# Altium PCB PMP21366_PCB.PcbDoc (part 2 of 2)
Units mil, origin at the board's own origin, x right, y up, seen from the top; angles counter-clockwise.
Board outline 5900 x 4700 mil, 2 copper layers (Top Layer, Bottom Layer), stack 62 mil thick; 89 components, 44 nets, 220 pads, 54 vias.
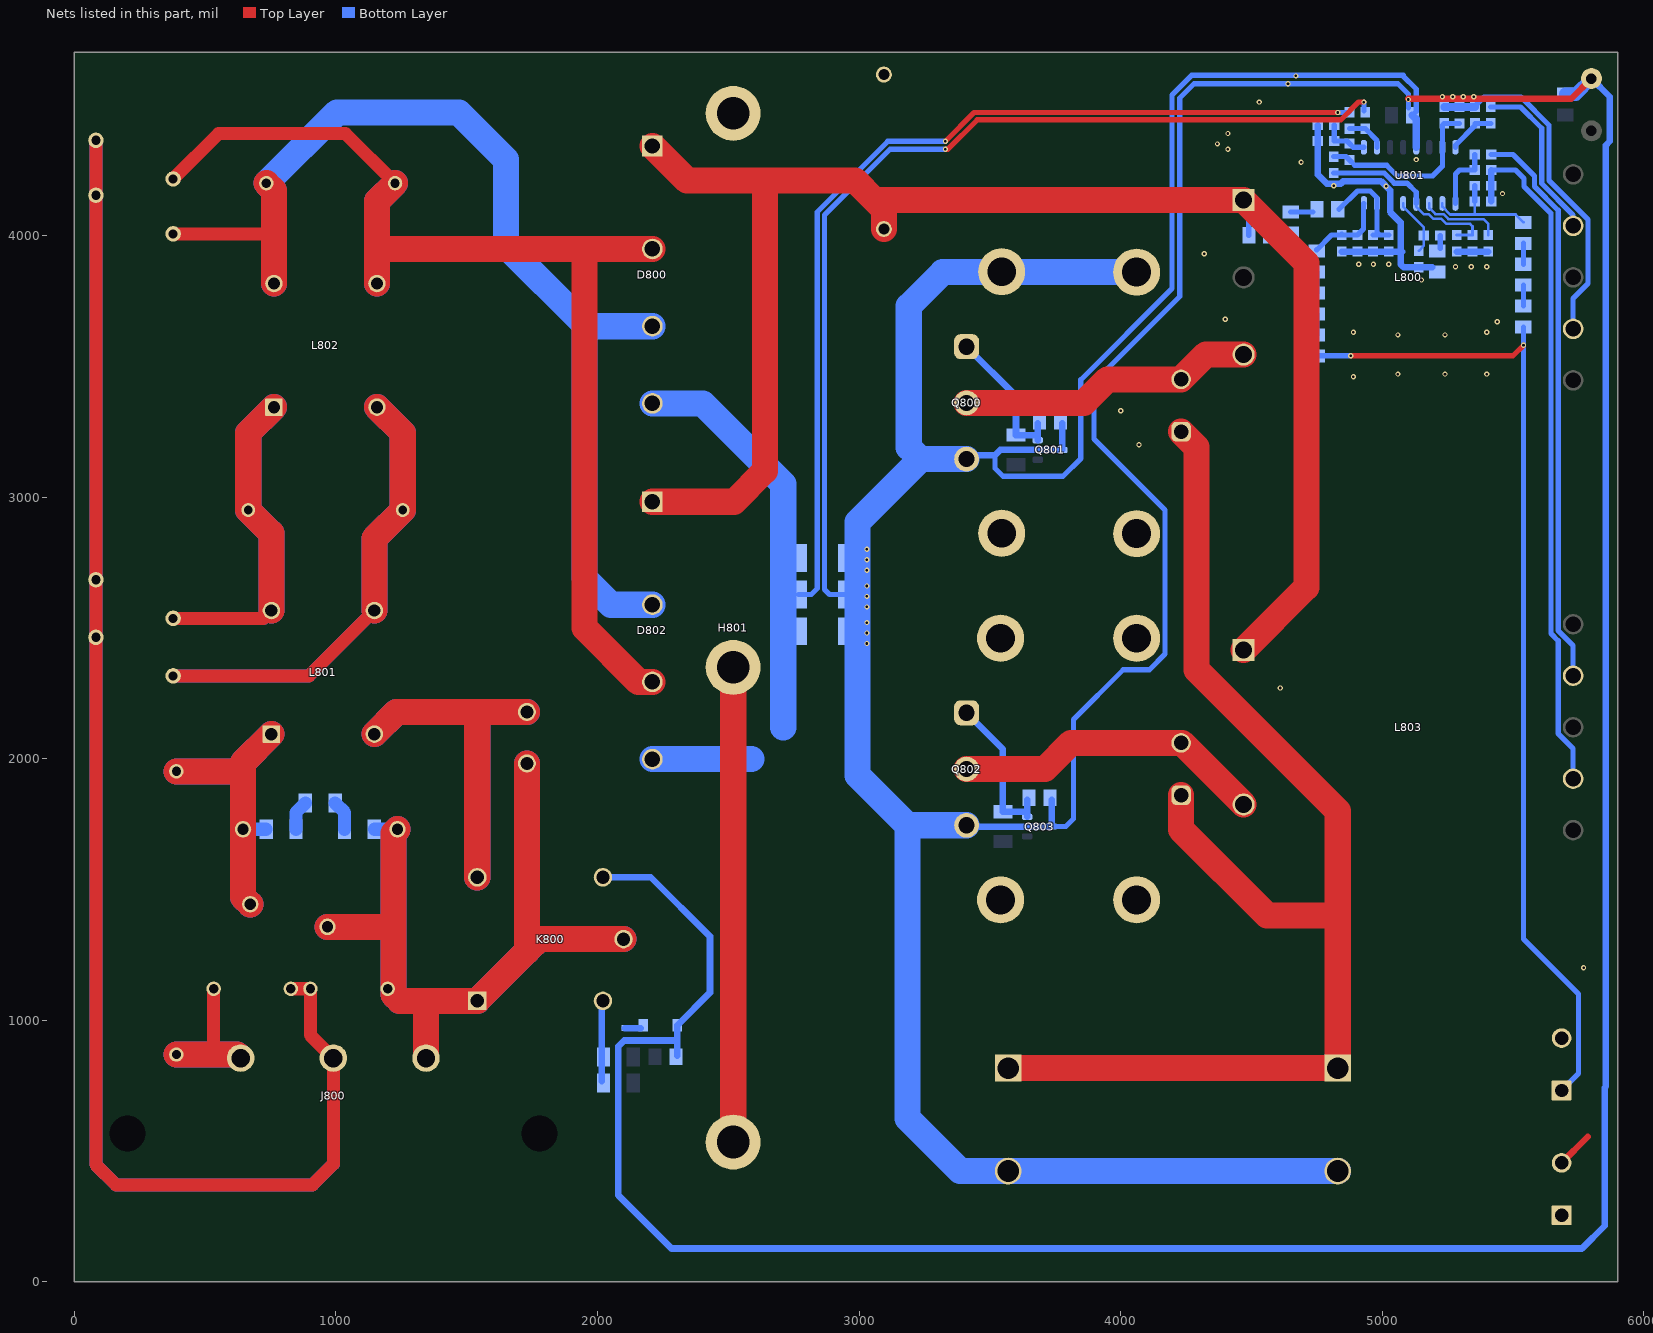
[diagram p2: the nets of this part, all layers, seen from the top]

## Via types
v1: diameter 20, hole 10, Top Layer to Bottom Layer, 54 vias

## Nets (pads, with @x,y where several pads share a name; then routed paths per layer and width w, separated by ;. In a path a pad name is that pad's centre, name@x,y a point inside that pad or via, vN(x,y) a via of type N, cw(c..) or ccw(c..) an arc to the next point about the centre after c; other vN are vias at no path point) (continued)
GND1: C810.2 C811.2 C812.2 C814.1 C815.2 C816.2 C817.2 C818.2 C819.2 C820.2 C821.2 C822.2 C823.2 C824.2 C825.2 C826.2 C827.2 D804.1 GND.1 H800.1 H800.2 H802.1 H802.2 H803.1 H803.2 H804.1 H804.2 J802.1 J802.2 K800.5 L800.5 L803.5 Q800.3 Q801.3 Q802.3 Q803.3 R803.2 R804.2 R805.2 R806.1 R814.1 R824.1 R829.1 R831.1 R832.1 R833.1 R834.1 U801.6 U801.13 | length 34843.4
  Top Layer w20: v1(3330,4330) 3339.42,4330 3451.55,4442.13 4841.55,4442.13 4909.42,4510 v1(4930,4510)
  Top Layer w25: v1@5100,4522.5 5722.5,4522.5 GND.1@5800,4600 ; J802.2@5685.67,454.26 5785.67,554.26
  Bottom Layer w20: R805.2@2950.55,2627.09 2887.56,2627.09 2867.87,2646.77 2867.87,4078.45 3119.42,4330 v1(3330,4330) ; 3520,3160 3520,3110 3550.55,3079.45 3779.45,3079.45 3847.87,3147.87 3847.87,3448.45 4196.75,3797.33 4196.75,4537.33 4271.55,4612.13 5080,4612.13 5080,4610 5130,4560 5130,4475 C817.2@5115,4460 ; Q803.3@3737.24,1740 3790,1740 3820,1770 3820,2150 4010,2340 4110,2340 4170,2400 4170,2950 3897.87,3222.13 3897.87,3439.03 4225.75,3766.91 4225.75,4525.75 4280,4580 5060,4580 5100,4540 v1(5100,4520) C817.2@5100,4488.54 ; C820.2@4930,4476.5 v1(4930,4510) ; C815.2@5355,4491.5 5355,4495.16 5388.9,4529.06 5530.36,4529.06 5637.87,4421.55 5637.87,4209.85 5787.17,4060.56 5787.17,3816.29 5729.92,3759.04 L800.5@5729.92,3643.15 ; C816.2@5416.5,4250 5510,4250 5542.13,4217.87 5542.13,4187.34 5644.8,4084.66 5644.8,2478.44 5672.68,2450.57 5672.68,2096.29 5729.92,2039.04 L803.5@5729.92,1923.15
  Bottom Layer w25: K800.5@2020.79,1546.22 2203.78,1546.22 2430,1320 2430,1105.53 D804.1@2304.47,980 2304.47,922.23 ; C814.1@2304.47,864.47 2304.47,922.23 ; Q802.3@3416,1740 Q803.3@3737.24,1740 R814.1@3737.24,1842.76 ; Q800.3@3426,3160 3520,3160 3540,3180 Q801.3@3777.24,3180 R806.1@3777.24,3282.76 ; C819.2@4753.5,4421.3 R829.1@4753.5,4361.3 4753.5,4232.8 4787.86,4198.44 4842.14,4198.44 4851.82,4208.13 4995,4208.13 5030,4173.13 U801.6@5030,4122.72 5030,4090 5070,4050 5070,3890 5081.5,3878.5 C823.2@5140,3878.5 C827.2@5191.5,3878.5 ; R831.1@4845,3938.5 C821.2@4905,3938.5 5076.5,3938.5 ; C826.2@5285,3938.5 R834.1@5345,3938.5 R833.1@5405,3938.5 ; C818.2@5416.5,4130 C816.2@5416.5,4250 ; GND.1@5800,4600 5870,4530 5870,4360 5855.37,4345.37 5855.37,747.03 5850.41,742.07 5850.41,213.92 5763.62,127.13 2282.87,127.13 2080,330 2080,900 2102.23,922.23 2304.47,922.23
  Bottom Layer w29.53: C817.2@5115,4460 5130,4445 U801.13@5130,4337.28 ; C825.2@5236.93,4491.5 C815.2@5355,4491.5
  Bottom Layer w50: C812.2@5700,4540 5740,4540 GND.1@5800,4600
  Bottom Layer w100: Q802.3@3411,1745 3185,1745 ; Q800.3@3411,3145 3235,3145 ; H800.2@4061,3860 3320,3860 3190,3730 3190,3190 3235,3145 ; C811.2@4830,423.15 C810.2@3570,423.15 3386.85,423.15 3185,625 3185,1745 ; 3185,1745 2994.6,1935.4 2994.6,2904.6 3235,3145
  other v1: 5770,1200 4610,2270 3030,2440 3030,2480 3030,2520 3030,2580 3030,2620 3030,2660 3030,2720 3030,2760 3030,2800 4070,3200 4000,3330 4890,3460 5060,3470 5240,3470 5400,3470 5060,3620 5240,3620 4890,3630 5400,3630 5440,3670 4400,3680 5150,3830 5280,3880 5340,3880 5400,3880 4910,3890 4966.31,3890.43 5025,3890 4320,3930 5460,4160 5015,4188.13 4815,4190 4690,4280 5130,4290 4410,4330 4370,4350 4410,4390 4530,4510 5230,4530 5270,4530 5310,4530 5350,4530 4640,4580 4670,4610
NetC801_2: C801.2 F800.2 J800.1 | length 1005.3
  Top Layer w50: 532.36,868.66 C801.2@532.36,1120
  Top Layer w100: F800.2@390,868.66 532.36,868.66 622.01,868.66 J800.1@635.67,855
  Bottom Layer w50: 532.36,868.66 C801.2@532.36,1120
  Bottom Layer w100: F800.2@390,868.66 532.36,868.66 622.01,868.66 J800.1@635.67,855
NetC802_2: C802.2 C805.1 L801.4 L802.1 | length 2485.8
  Top Layer w50: C802.2@377.64,2536.18 723.11,2536.18 L801.4@753.15,2566.22
  Top Layer w100: L801.4@753.15,2566.22 753.15,2861.57 C805.1@664.72,2950 664.72,3245.35 L802.1@763.15,3343.78
  Bottom Layer w50: C802.2@377.64,2536.18 723.11,2536.18 L801.4@753.15,2566.22
  Bottom Layer w100: L801.4@753.15,2566.22 753.15,2861.57 C805.1@664.72,2950 664.72,3245.35 L802.1@763.15,3343.78
NetC803_2: C803.2 C806.1 D800.3 D802.2 L802.4 | length 4545.1
  Top Layer w50: C803.2@377.64,4006.18 739.33,4006.18
  Top Layer w100: C806.1@733.94,4200 763.15,4170.79 L802.4@763.15,3816.22
  Bottom Layer w100: L802.4@763.15,3816.22 763.15,4170.79 C806.1@733.94,4200 1003.94,4470 1470,4470 1650,4290 1650,3960 1950,3660 ; D802.2@2210,2588.43 2051.57,2588.43 1950,2690 1950,3660 ; D800.3@2210,3653.15 1956.85,3653.15 1950,3660
NetC804_1: C804.1 F800.1 L801.1 R800.2 RV800.2 | length 1945.9
  Top Layer w100: F800.1@390,1951.34 613.39,1951.34 ; RV800.2@672.36,1443.31 644.72,1470.94 C804.1@644.72,1730 644.72,1985.35 L801.1@753.15,2093.78
  Bottom Layer w50: C804.1@644.72,1730 R800.2@732.91,1730
  Bottom Layer w100: F800.1@390,1951.34 610.71,1951.34 ; RV800.2@672.36,1443.31 644.72,1470.94 C804.1@644.72,1730 644.72,1985.35 L801.1@753.15,2093.78
NetC804_2: C804.2 C807.1 J800.2 K800.1 K800.3 R807.1 R808.2 RV800.1 | length 5824.2
  Top Layer w50: 1243.86,1073.78 1249.53,1068.11 1344.33,1068.11
  Top Layer w100: RV800.1@967.64,1356.69 1213.31,1356.69 1220,1350 ; C804.2@1235.28,1730 1220,1714.72 1220,1350 ; J800.2@1344.33,855 1344.33,1068.11 ; R808.2@1730,1981.57 1730,1263.31 ; K800.3@2099.53,1310 1776.69,1310 1730,1263.31 ; 1220,1350 1220,1097.64 1243.86,1073.78 K800.1@1540.47,1073.78 1730,1263.31
  Bottom Layer w50: R807.1@1147.09,1730 C804.2@1235.28,1730
  Bottom Layer w100: RV800.1@967.64,1356.69 1220,1356.69 ; C804.2@1235.28,1730 1220,1714.72 1220,1356.69 ; J800.2@1344.33,855 1344.33,1060.87 1357.24,1073.78 ; R808.2@1730,1981.57 1730,1263.31 ; K800.3@2099.53,1310 1776.69,1310 1730,1263.31 ; 1220,1356.69 1220,1097.64 1243.86,1073.78 1357.24,1073.78 ; 1357.24,1073.78 K800.1@1540.47,1073.78 1730,1263.31
NetC805_2: C805.2 C808.1 L801.3 L802.2 | length 3472
  Top Layer w50: C808.1@377.64,2316.18 896.81,2316.18 L801.3@1146.85,2566.22
  Top Layer w100: L801.3@1146.85,2566.22 1146.85,2841.57 C805.2@1255.28,2950 1255.28,3245.35 L802.2@1156.85,3343.78
  Bottom Layer w50: C808.1@377.64,2316.18 896.81,2316.18 L801.3@1146.85,2566.22
  Bottom Layer w100: L801.3@1146.85,2566.22 1146.85,2841.57 C805.2@1255.28,2950 1255.28,3245.35 L802.2@1156.85,3343.78
NetC806_2: C806.2 C809.1 D800.2 D802.3 L802.3 | length 4669.7
  Top Layer w50: C809.1@377.64,4216.18 551.46,4390 1036.06,4390 C806.2@1226.06,4200
  Top Layer w100: L802.3@1156.85,3816.22 1156.85,4130.79 C806.2@1226.06,4200 ; 1158.43,3948.43 1950,3948.43 ; D802.3@2210,2293.15 2156.85,2293.15 1950,2500 1950,3948.43 ; D800.2@2210,3948.43 1950,3948.43
  Bottom Layer w100: L802.3@1156.85,3816.22 1156.85,4130.79 C806.2@1226.06,4200
NetC815_1: C815.1 R815.2 U801.16 | length 182.3
  Bottom Layer w20: U801.16@5280,4337.28 5280,4345 5355,4420 C815.1@5355,4428.5 R815.2@5415,4428.5
NetC816_1: C816.1 R816.1 U801.1 | length 252
  Bottom Layer w20: U801.1@5280,4122.72 5280,4235 5295,4250 C816.1@5353.5,4250 R816.1@5353.5,4310
NetC818_1: C818.1 R821.1 R824.2 U801.2 | length 457.6
  Bottom Layer w10: U801.2@5230,4122.72 5230,4110 5260,4080 5353.5,4080 ; C818.1@5353.5,4130 5353.5,4080 ; R821.1@5540,4050 5510,4080 5353.5,4080
  Bottom Layer w20: C818.1@5353.5,4130 R824.2@5353.5,4190
NetC819_1: C819.1 R829.2 R835.2 U801.9 | length 183.5
  Bottom Layer w20: C819.1@4816.5,4421.3 R829.2@4816.5,4361.3 4865.2,4361.3 R835.2@4875,4351.5 4889.21,4337.28 U801.9@4930,4337.28
NetC820_1: C820.1 R828.2 U801.10 | length 149.9
  Bottom Layer w20: R828.2@4875,4408.5 C820.1@4935,4408.5 4980,4363.5 U801.10@4980,4337.28
NetC821_1: C821.1 R826.1 R831.2 U801.8 | length 313.5
  Bottom Layer w20: R826.1@4750,3945 4806.5,4001.5 R831.2@4845,4001.5 ; R831.2@4845,4005 R831.2@4845,4001.5 ; U801.8@4930,4122.72 4928.43,4121.14 4928.43,4024.92 C821.1@4905,4001.5 R831.2@4845,4001.5
NetC822_1: C822.1 R827.1 R832.2 U801.7 | length 391.7
  Bottom Layer w20: R827.1@4835,4100 4905.17,4170.17 4954.05,4170.17 4980,4144.22 U801.7@4980,4122.72 4980,4011.5 4990,4001.5 ; C822.1@4965,4001.5 R832.2@5025,4001.5
NetC823_1: C823.1 R830.2 U801.5 | length 221.4
  Bottom Layer w10: U801.5@5080,4122.72 5080,4110 5158.5,4031.5 R830.2@5158.5,4000 5158.5,3960 C823.1@5140,3941.5
NetC824_1: C824.1 C825.1 R825.1 R835.1 U801.15 | length 685.1
  Bottom Layer w20: R825.1@4815,4301.5 4862.01,4301.5 R835.1@4875,4288.5 4895,4268.5 5017,4268.5 5057.63,4227.87 5192.87,4227.87 5230,4265 U801.15@5230,4337.28 5230,4421.58 5236.4,4427.97 C824.1@5295,4427.97
NetC826_1: C826.1 R825.2 R834.2 U801.4 | length 740
  Bottom Layer w10: U801.4@5130,4122.72 5130,4110 5158.7,4081.3 5177.75,4081.3 5195.63,4063.43 5226.02,4063.43 5245.19,4044.25 5335.75,4044.25 5345,4035 R834.2@5345,4001.5
  Bottom Layer w12: C826.1@5285,4001.5 R834.2@5345,4001.5
  Bottom Layer w20: R825.2@4815,4238.5 5007.58,4238.5 5046.09,4200 5095,4200 5130,4165 U801.4@5130,4122.72
NetC827_1: C827.1 R830.1 | length 48.5
  Bottom Layer w20: C827.1@5221.5,3951.5 R830.1@5221.5,4000
NetD801_3: D801.3 L800.3 Q800.2 | length 1135.6
  Top Layer w100: Q800.2@3411,3360 3860,3360 3950,3450 D801.3@4231,3450 4325.72,3544.72 L800.3@4470.08,3544.72
NetD803_3: D803.3 L803.3 Q802.2 | length 1198
  Top Layer w100: Q802.2@3411,1960 3710,1960 3810,2060 D803.3@4231,2060 4234.8,2060 L803.3@4470.08,1824.72
NetD804_2: D804.2 D805.2 | length 62.2
  Bottom Layer w25: D805.2@2103.31,970 D804.2@2165.53,970
NetD805_1: D805.1 K800.4 R810.1 R811.1 | length 303.5
  Bottom Layer w25: R811.1@2016.69,766.22 D805.1@2016.69,970 K800.4@2016.69,1069.68
NetK800_2: K800.2 L801.2 R808.1 | length 2484
  Top Layer w100: L801.2@1146.85,2093.78 1231.5,2178.43 R808.1@1730,2178.43 ; K800.2@1540.47,1546.22 1540.47,2171.1
  Bottom Layer w100: L801.2@1146.85,2093.78 1231.5,2178.43 R808.1@1730,2178.43 ; K800.2@1540.47,1546.22 1540.47,2168.9
NetQ800_1: Q800.1 Q801.2 R801.2 R806.2 | length 561.4
  Bottom Layer w25: Q800.1@3411,3575 3600,3386 R801.2@3600,3237.09 3679.84,3237.09 ; Q801.2@3682.76,3217.4 R806.2@3682.76,3282.76
NetQ802_1: Q802.1 Q803.2 R812.2 R814.2 | length 590.7
  Bottom Layer w25: Q802.1@3411,2175 3550,2036 R812.2@3550,1797.09 3639.84,1797.09 ; Q803.2@3642.76,1777.4 R814.2@3642.76,1842.76
NetR800_1: R800.1 R802.2 | length 114.8
  Bottom Layer w50: R800.1@847.09,1730 847.09,1794.17 R802.2@882.91,1830
NetR802_1: R802.1 R807.2 | length 114.8
  Bottom Layer w50: R802.1@997.09,1830 1032.91,1794.17 R807.2@1032.91,1730
NetR817_1: R817.1 R818.2 | length 80
  Bottom Layer w20: R817.1@5540,3730 R818.2@5540,3810
NetR818_1: R818.1 R821.2 | length 80
  Bottom Layer w20: R818.1@5540,3890 R821.2@5540,3970
NetR819_1: R819.1 R822.2 | length 80
  Bottom Layer w20: R819.1@4750,3620 R822.2@4750,3700
NetR820_1: R820.1 R823.2 | length 70
  Bottom Layer w20: R820.1@4580,4010 R823.2@4650,4010
NetR822_1: R822.1 R826.2 | length 80
  Bottom Layer w20: R822.1@4750,3780 R826.2@4750,3860
NetR823_1: R823.1 R827.2 | length 85
  Bottom Layer w20: R823.1@4650,4090 R827.2@4735,4090
NetR833_2: R833.2 U801.3 | length 311.5
  Bottom Layer w10: U801.3@5180,4122.72 5180,4104.33 5203.03,4081.3 5233.42,4081.3 5252.6,4062.13 5387.87,4062.13 5405,4045 R833.2@5405,4001.5
PE: C801.1 C802.1 C803.1 C807.2 C808.2 C809.2 J800.3 | length 10964.3
  Top Layer w50: C809.2@82.36,4363.82 C803.1@82.36,4153.82 C802.1@82.36,2683.82 C808.2@82.36,2463.82 82.36,447.64 160,370 910,370 990,450 J800.3@990,855 902.36,942.64 C807.2@902.36,1120 C801.1@827.64,1120
  Bottom Layer w50: C809.2@82.36,4363.82 C803.1@82.36,4153.82 C802.1@82.36,2683.82 C808.2@82.36,2463.82 82.36,447.64 160,370 910,370 990,450 J800.3@990,855
VAC: C800.1 D800.1 D802.1 L800.1 L803.1 R820.2 | length 6093.9
  Top Layer w100: D802.1@2210,2982.13 2522.13,2982.13 2640,3100 2640,4210 ; D800.1@2210,4342.13 2342.13,4210 2640,4210 ; C800.1@3094.72,4024.72 3094.72,4100 3059.45,4135.28 ; L803.1@4470.08,2415.28 4710,2655.2 4710,3895.35 L800.1@4470.08,4135.28 3059.45,4135.28 ; 2640,4210 2984.72,4210 3059.45,4135.28
  Bottom Layer w20: R820.2@4490,4000 L800.1@4490,4115.35
VBulk: C810.1 C811.1 D801.1 D803.1 J801.1 J801.2 R817.2 R819.2 | length 8646.4
  Top Layer w20: v1(4880,3540) 5500,3540 v1(5540,3580)
  Top Layer w100: C810.1@3570,816.85 C811.1@4830,816.85 4830,1400 ; D803.1@4231,1860 4231,1729 4560,1400 4830,1400 ; D801.1@4231,3250 4290,3191 4290,2339.45 4830,1799.45 4830,1400
  Bottom Layer w20: R819.2@4750,3540 v1(4880,3540) ; R817.2@5540,3650 v1(5540,3580) 5540,1310 5750,1100 5750,795.64 J801.1@5685.67,731.31
VN: C800.2 D800.4 D802.4 H801.1 H801.2 H801.3 R803.1 R804.1 R805.1 R828.1 | length 7461.3
  Top Layer w20: v1(3330,4360) 3440,4470 v1(4830,4470)
  Top Layer w100: H801.1@2518.66,533.9 H801.2@2518.66,2348.86
  Bottom Layer w20: R805.1@2769.45,2627.09 2817.09,2627.09 2840,2650 2840,4090 3110,4360 v1(3330,4360) ; v1(4830,4470) R828.1@4873.5,4470
  Bottom Layer w100: D802.4@2210,1997.87 2587.87,1997.87 ; D800.4@2210,3357.87 2402.13,3357.87 2710,3050 2710,2120
ZCD1: L800.7 R815.1 | length 651.6
  Bottom Layer w20: R815.1@5415,4491.5 5528.5,4491.5 5610,4410 5610,4198.31 5729.92,4078.39 L800.7@5729.92,4036.85
ZCD2: L803.7 R816.2 | length 2171.9
  Bottom Layer w20: R816.2@5416.5,4310 5500,4310 5582.13,4227.87 5582.13,4186.76 5672.68,4096.21 5672.68,2489.99 5729.92,2432.75 L803.7@5729.92,2316.85
pads on no net: J800.MH1 J800.MH2 L800.2 L800.4 L800.6 L800.8 L803.4 L803.6 L803.8

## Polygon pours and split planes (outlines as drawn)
GND1 on Bottom Layer "GND1" (solid, pour order 28): 5890,30 5870,10 2170,10 1940,240 1940,1060 1990,1110 2500,1110 2900,1510 2900,4070 3130,4300 4277.87,4300 4530,4552.13 4530,4650 5860,4650 5890,4620
VN on Bottom Layer "VN" (solid, pour order 14): 2180,3410 2160,3390 2160,3320 2410,3070 2410,2400 2410,2160 2340,2090 2180,2090 2160,2070 2160,1780 2500,1440 2690,1440 2710,1460 2710,1850 2750,1890 2750,4070 3080,4400 3140,4460 3140,4670 3120,4690 2420,4690 2400,4670 2400,3480 2330,3410
NetC803_2 on Bottom Layer "C803_2" (solid, pour order 0): 810,3760 830,3780 830,4160 1060,4390 1360,4390 1460,4290 1460,3530 1600,3390 1600,2670 1770,2500 2240,2500 2260,2520 2260,2700 2240,2720 2130,2720 2030,2820 2030,3460 2140,3570 2240,3570 2260,3590 2260,3720 2240,3740 2170,3740 2030,3880 2030,4450 1810,4670 720,4670 600,4550 600,3780 620,3760
GND1 on Top Layer "GND1" (solid, pour order 30): 5890,30 5870,10 2170,10 1940,240 1940,1060 1990,1110 2500,1110 2900,1510 2900,4070 3130,4300 4300,4300 4650,4650 5860,4650 5890,4620
VBulk on Top Layer "VBULK" (solid, pour order 24): 4170,3300 4160,3290 4160,2340 4600,1900 4600,1770 4580,1750 4410,1750 4250,1910 4170,1910 4150,1890 4150,1590 4210,1530 4210,1380 3990,1160 3610,1160 3480,1030 3480,770 3530,720 5590,720 5630,680 5720,680 5730,690 5730,950 4930,1750 4930,1810 4390,2350 4390,3220 4310,3300
VAC on Top Layer "VAC" (solid, pour order 22): 2230,3100 2160,3030 2160,2880 2170,2870 2770,2870 2960,3060 2960,3680 3290,4010 4450,4010 4560,3900 4560,2640 4420,2500 4420,2370 4440,2350 4700,2350 4820,2470 4820,4010 4570,4260 3180,4260 3100,4340 2430,4340 2340,4430 2170,4430 2160,4420 2160,4310 2447,4023 2447,3100
NetC806_2 on Top Layer "C806_2" (solid, pour order 2): 1110,3750 1080,3780 1080,4270 1150,4340 1890,4340 2260,3970 2260,3900 2240,3880 2180,3880 2010,3710 2010,2528.98 2168.98,2370 2240,2370 2260,2350 2260,2240 2240,2220 1860,2220 1560,2520 1560,3450 1260,3750
VN on Top Layer "VN" (solid, pour order 20): 2430,410 2390,450 2390,2140 2410,2160 2410,2433 2447,2470 2590,2470 2630,2430 2630,450 2590,410

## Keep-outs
Keep-Out Layer:
  text ".Layer_Name" at 577,-858.49 h60

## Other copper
Top Layer:
  text ".Layer_Name" at 577,-858.49 h60
Bottom Layer:
  text ".Layer_Name" at 577,-858.49 h60

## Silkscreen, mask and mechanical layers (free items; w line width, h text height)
Top Overlay:
  region: 3080,110 2780,110 2780,10 3080,10
  text "PMP21366 RevB" at 2010,30 h108.27
  text ".Layer_Name" at 577,-858.49 h60
Bottom Overlay:
  lines w10: 4380,4440 4640,4440 4680,4400 ; 5080,3820 5080,3970 5110,4000 ; 3910,4240 3910,4580 3960,4630 4110,4630 4290,4630 4380,4540 4380,4213.5 4326.5,4160 4140,4160 3990,4160 3910,4240
  text ".Layer_Name" at 577,-858.49 h60
Top Paste:
  text ".Layer_Name" at 577,-858.49 h60
Bottom Paste:
  text ".Layer_Name" at 577,-858.49 h60
Top Solder:
  text ".Layer_Name" at 577,-858.49 h60
  text ".Layer_Name" at 577,-858.49 h60
Bottom Solder:
  text ".Layer_Name" at 577,-858.49 h60
Drill Guide:
  text ".Layer_Name" at 577,-858.49 h60
M1 Board Outline:
  the board outline again, w7
  text ".Layer_Name" at 577,-858.49 h60
M2 Board Dimensions:
  rectangle: 0,-275 125,-150
  rectangle: 125,-400 500,-275
  lines w7: 0,-275 1000,-275 ; 125,-400 125,-150 ; 250,-400 250,-150 ; 500,-400 500,-150 ; 750,-400 750,-150 ; 0,-400 1000,-400 1000,-150 0,-150 0,-400
  text ".Layer_Name" at 577,-858.49 h60
M3 3D STEP Top:
  text ".Layer_Name" at 577,-858.49 h60
M4 3D STEP Bottom:
  text ".Layer_Name" at 577,-858.49 h60
M5 Assembly Top:
  lines w10: -292,-930.17 6308,-930.17 ; -292,-726.83 6310,-726.83 ; -292,-523.5 -292,-1133.5 3713,-1133.5 6310,-1133.5 6310,-523.5 -291.5,-523.5 -291.5,-1133.5 1284,-1133.5 ; 2173,-1133.5 2173,-523.5 ; 3440,-726.83 3440,-523.5 ; 4280,-726.83 4280,-523.5 ; 4902,-1140 4902,-937.17
  text "COMPONENTS MARKED 'DNP' SHOULD NOT BE POPULATED." at 1153.5,-318.5 h60
  text "ASSEMBLY VARIANT:" at 1153,-434 h60
  text ".VariantName" at 2189,-434 h60
  text "PCB VIEWED FROM TOP SIDE" at -228.5,-655.67 h60
  text "BOARD #:" at 2248,-655.67 h60
  text ".PRJ_Number" at 2793.5,-655.67 h60
  text "REV:" at 3638,-655.67 h60
  text ".PCB_Rev" at 3929.5,-655.67 h60
  text "SVN REV:" at 4476,-655.67 h60
  text ".VersionControl_RevNumber" at 4982,-655.67 h60
  text "TID #:" at 2248,-859 h60
  text ".TID" at 2793.5,-859 h60
  text "PLOT NAME =" at -228.5,-1064.34 h60
  text ".plot_File_Name" at 577,-1064.34 h60
  text "GENERATED    :" at 2250,-1064.34 h60
  text ".Print_Date" at 3119.5,-1064.34 h60
  text ".Print_Time" at 3848.5,-1064.34 h60
  text "TEXAS INSTRUMENTS" at 5113,-1064.34 h60
M6 Assembly Bottom:
  lines w10: -292.5,-727.33 6309.5,-727.33 ; -290.5,-930.67 6309.5,-930.67 ; 1115.5,-1140.5 1115.5,-937.67 ; 1737.5,-727.33 1737.5,-524 ; 2577.5,-727.33 2577.5,-524 ; 3844.5,-1134 3844.5,-524 ; 4733.5,-1134 6309,-1134 6309,-524 -292.5,-524 -292.5,-1134 2304.5,-1134 6309.5,-1134 6309.5,-524
  text "COMPONENTS MARKED 'DNP' SHOULD NOT BE POPULATED." at 6102,-318 h60
  text ".VariantName" at 5058,-434 h60
  text "ASSEMBLY VARIANT:" at 6097,-434 h60
  text ".VersionControl_RevNumber" at 1035.5,-656.17 h60
  text "SVN REV:" at 1541.5,-656.17 h60
  text ".PCB_Rev" at 2088,-656.17 h60
  text "REV:" at 2379.5,-656.17 h60
  text ".PRJ_Number" at 3224,-656.17 h60
  text "BOARD #:" at 3769.5,-656.17 h60
  text "PCB VIEWED FROM BOTTOM SIDE" at 6246,-656.17 h60
  text ".TID" at 3224,-859.5 h60
  text "TID #:" at 3769.5,-859.5 h60
  text "TEXAS INSTRUMENTS" at 904.5,-1064.84 h60
  text ".Print_Time" at 2169,-1064.84 h60
  text ".Print_Date" at 2898,-1064.84 h60
  text "GENERATED    :" at 3767.5,-1064.84 h60
  text ".plot_File_Name" at 5440.5,-1064.84 h60
  text "PLOT NAME =" at 6246,-1064.84 h60
M9 Title Sheet:
  drawing of 57 lines, arcs and shapes, not listed
  text "1" at 739.84,8036.5 h70
  text "2" at 3235.5,8036.5 h70
  text "3" at 5724.84,8036.5 h70
  text "4" at 8231.51,8036.5 h70
  text "5" at 10730.5,8036.5 h70
  text "6" at 13235.5,8036.5 h70
  text "A" at -416.5,6893.5 h70
  text "A" at 14383.5,6893.5 h70
  text "B" at -416.5,4513.5 h70
  text "B" at 14383.5,4513.5 h70
  text "C" at -416.5,2138.5 h70
  text "C" at 14383.5,2138.5 h70
  text "PROJECT TITLE:" at 11343.5,277.5 h45
  text ".PRJ_Title" at 11393.5,144.17 h70
  text "DESIGNED FOR:" at 11343.5,-23.5 h45
  text ".PRJ_Customer" at 11393.5,-163.5 h70
  text "D" at -416.5,-231.5 h70
  text "D" at 14383.5,-231.5 h70
  text "FILE NAME:" at 11343.5,-323.5 h45
  text ".PCB_File_Name_No_Path" at 11393.5,-443.5 h70
  text "Texas Instruments (TI) and/or its licensors do not warrant the accuracy or completeness of this specification" at 6374,-605.34 h45
  text "ENGINEER:" at 11343.5,-613.5 h45
  text "LAYOUT BY:" at 12848.5,-613.5 h45
  text "or any information contained therein. TI and/or its licensors do not warrant that this design will meet" at 6329.01,-718 h45
  text ".PRJ_Engineer" at 11393.5,-768.49 h70
  text ".PCB_Layout" at 12899,-768.49 h70
  text "the specifications, will be suitable for your application or fit for any particular purpose, or will operate in" at 6329.01,-830.67 h45
  text ".Layer_Name" at 577,-858.49 h60
  text "ALTIUM DESIGNER VERSION:" at 12848.5,-923.5 h45
  text "an implementation. TI and/or its licensors do not warrant that the design is production worthy. You should" at 6329.01,-943.33 h45
  text "completely validate and test your design implementation to confirm the system functionality for your application." at 6374,-1056 h45
  text ".print_Scale" at 11393.5,-1056.83 h70
  text ".Application_BuildNumber" at 12899,-1056.83 h70
  text "1" at 739.84,-1263.5 h70
  text "2" at 3235.5,-1263.5 h70
  text "3" at 5724.84,-1263.5 h70
  text "4" at 8231.51,-1263.5 h70
  text "5" at 10730.5,-1263.5 h70
  text "6" at 13235.5,-1263.5 h70
M10 Fab Notes:
  drawing of 173 lines, arcs and shapes, not listed
  text "DESIGN INFORMATION" at 12378.02,6201 h60
  text "MIN. TRACK WIDTH:" at 11733.46,6021 h60
  text "8" at 12829.7,6021 h60
  text "MIL" at 12984.46,6021 h60
  text "MIN. CLEARANCE:" at 11733.46,5889 h60
  text "0.2" at 12769.7,5889 h60
  text "mm" at 12984.46,5889 h60
  text "MIN. VIA PAD SIZE:" at 11733.46,5757 h60
  text "24" at 12799.71,5757 h60
  text "MIL" at 12984.46,5757 h60
  text "0.05mm (2MIL)" at 12428.46,5615.29 h60
  text "MINIMUM ANNULAR RING" at 11404.23,5611 h60
  text "EXTERNAL" at 13136.46,5611 h60
  text "PER" at 11604.23,5493 h60
  text "IPC-D-275 CLASS 2 LEVEL C" at 11824.23,5493 h60
  text "MIL, HOLES" at 13312.46,5380.71 h60
  text "+/-" at 12920,5380 h60
  text "+/-" at 13774,5380 h60
  text "REGISTRATION TOLERANCES:" at 11404.23,5375 h60
  text "METAL" at 12604,5375 h60
  text "5" at 13180.2,5375 h60
  text "3" at 14013.2,5375 h60
  text "MIL" at 14129.46,5375 h60
  text "+/-" at 13774,5262 h60
  text "HOLE SIZE TOLERANCE (UNLESS OTHERWISE SPECIFIED):" at 11404.23,5257 h60
  text "3" at 14013.2,5257 h60
  text "MIL" at 14129.46,5257 h60
  text "MATERIAL:" at 11329.46,5047.54 h60
  text "FR-4 High Tg" at 12315.9,4907.21 h60
  text "FR-408" at 11750.46,4898.64 h60
  text "OTHER" at 13238.46,4898.64 h60
  text "X" at 12161,4895 h60
  text "62 MIL (1.6mm) +/-10%" at 12070.56,4735.92 h60
  text "THICKNESS:" at 11404.23,4731.64 h60
  text "X" at 11942.4,4731.64 h60
  text "OTHER" at 13355.46,4731.64 h60
  text "TOLERANCE:" at 11404.23,4573.64 h60
  text "X" at 12243.53,4573.64 h60
  text "ANSI IPC-6012 TYPE 3 CLASS 2" at 12430.48,4573.64 h60
  text "OTHER +/-" at 12430.46,4417.64 h60
  text "BOW & TWIST:" at 11404.23,4260.64 h60
  text "X" at 12243.53,4260.64 h60
  text "ANSI IPC-6012 TYPE 3 CLASS 2" at 12430.48,4260.64 h60
  text "OTHER +/-" at 12430.46,4102.13 h60
  text "DRILLING:" at 11329.46,3963.64 h60
  text "REFERENCE:" at 11404.23,3846.64 h60
  text "X" at 12052.46,3846.64 h60
  text "AS SHOWN" at 12239.46,3846.64 h60
  text "X" at 12953.46,3846.64 h60
  text "NC_DRILL FILES" at 13090.46,3846.64 h60
  text "PTH COPPER THICKNESS:" at 11404.23,3688.64 h60
  text "X" at 12534.46,3688.64 h60
  text "20-30 um" at 12671.46,3688.64 h60
  text "OTHER" at 13388.46,3688.64 h60
  text "BOARD FINISH:" at 11329.46,3529.64 h60
  text "SILKSCREEN:" at 11484.68,3411.64 h60
  text "X" at 12433.46,3411.64 h60
  text "TOP" at 12559.46,3411.64 h60
  text "X" at 12943.46,3411.64 h60
  text "BOTTOM" at 13070.46,3411.64 h60
  text "SILKSCREEN COLOR:" at 11484.68,3244.64 h60
  text "X" at 12432.42,3244.64 h60
  text "WHITE" at 12559.46,3244.64 h60
  text "OTHER" at 13070.46,3244.64 h60
  text "X" at 12563.42,3085.44 h60
  text "GREEN" at 12690.46,3085.44 h60
  text "OTHER" at 13308.46,3085.44 h60
  text "SOLDER RESIST COLOR:" at 11484.68,3074.64 h60
  text "X" at 12563.42,2915.44 h60
  text "MATTE" at 12690.46,2915.44 h60
  text "SEMI-GLOSS" at 13308,2914.8 h60
  text "IMMERSION GOLD (ENIG)" at 12390.46,2726.92 h60
  text "ENEPIG" at 13728,2723.64 h60
  text "SURFACE FINISH:" at 11329.46,2722.64 h60
  text "X" at 12203.51,2722.64 h60
  text "IMM. TIN/SILVER OR EQUIV" at 11659,2565.64 h60
  text "OTHER" at 13090.46,2565.64 h60
  text "ARRAY/PANEL:" at 11329.46,2386.64 h60
  text "CUT AND TRIM PER M1 BOARD OUTLINE" at 12390.46,2382.35 h60
  text "N.C. ROUTE" at 12390.46,2230.64 h60
  text "X" at 13069.46,2230.64 h60
  text "V. SCORE" at 13256.46,2230.64 h60
  text "CERTIFICATION:" at 11329.46,2093.64 h60
  text "MATERIALS AND WORKMANSHIP FOR ALL PCBS" at 12054.46,2093.64 h60
  text "TO MEET OR EXCEED THE REQUIREMENTS OF:" at 12054.46,1995.64 h60
  text "X" at 11680.96,1859.13 h60
  text "ANSI IPC-A-600F CLASS ->" at 11819.96,1859.13 h60
  text "X" at 13459.02,1859.13 h60
  text "2" at 13577.96,1859.14 h60
  text "1" at 13262.96,1857.64 h60
  text "3" at 13931.96,1857.64 h60
  text "X" at 12495.02,1699.64 h60
  text "RoHS" at 12631.96,1699.64 h60
  text "OTHER" at 13276.36,1699.64 h60
  text "PER ORDER" at 13673.42,1699.64 h60
  text "ALL BOARDS MUST MEET OR EXCEED UL94-V0 REQUIREMENTS." at 11357,1534 h60
  text "PCB MUST BEAR THE UL94V-0 UL REGISTERED MATERIAL ID NUMBER" at 11357,1414 h60
  text "ADDITIONAL REQUIREMENTS:" at 11329.46,1240.64 h60
  text "MICROSECTION:" at 11404.23,1125.64 h60
  text "YES" at 12309.96,1125.64 h60
  text "REQUIRED" at 13171.46,969.49 h60
  text "BARE BOARD ELEC. TEST:" at 11404.23,966.64 h60
  text "NONE" at 12709.96,966.64 h60
  text "X" at 13044.46,966.64 h60
  text "PER ORDER" at 13763.46,966.64 h60
  text ".Layer_Name" at 577,-858.49 h60
M11 Gerber Information:
  lines w10: -292,-930.17 6308,-930.17 ; -292,-726.83 6310,-726.83 ; -292,-523.5 -292,-1133.5 3713,-1133.5 6310,-1133.5 6310,-523.5 -291.5,-523.5 -291.5,-1133.5 1284,-1133.5 ; 2173,-1133.5 2173,-523.5 ; 3440,-726.83 3440,-523.5 ; 4280,-726.83 4280,-523.5 ; 4902,-1140 4902,-937.17
  text "ALL ARTWORK VIEWED FROM TOP SIDE" at -228.5,-655.67 h60
  text "BOARD #:" at 2248,-655.67 h60
  text ".PRJ_Number" at 2793.5,-655.67 h60
  text "REV:" at 3638,-655.67 h60
  text ".PCB_Rev" at 3929.5,-655.67 h60
  text "SVN REV:" at 4476,-655.67 h60
  text ".VersionControl_RevNumber" at 4982,-655.67 h60
  text "LAYER NAME =" at -228.5,-858.49 h60
  text "TID #:" at 2248,-859 h60
  text ".TID" at 2793.5,-859 h60
  text "PLOT NAME =" at -228.5,-1064.34 h60
  text ".plot_File_Name" at 577,-1064.34 h60
  text "GENERATED    :" at 2250,-1064.34 h60
  text ".Print_Date" at 3119.5,-1064.34 h60
  text ".Print_Time" at 3848.5,-1064.34 h60
  text "TEXAS INSTRUMENTS" at 5113,-1064.34 h60
M12 Stackup:
  drawing of 191 lines, arcs and shapes, not listed
  text "Layer" at 9750.58,7610 h60
  text "Name" at 10160.49,7610 h60
  text "Material" at 11090.23,7610 h60
  text "Thickness" at 11950,7610 h60
  text "Constant" at 12599.84,7610 h60
  text "Board Layer Stack" at 13169.7,7610 h60
  text "1" at 9750.58,7490 h60
  text "Top Overlay" at 10160.49,7490 h60
  text "2" at 9750.58,7370 h60
  text "Top Solder" at 10160.49,7370 h60
  text "Solder Resist" at 11090.23,7370 h60
  text "0.40mil" at 11950,7370 h60
  text "3.5" at 12599.84,7370 h60
  text "3" at 9750.58,7250 h60
  text "Top Layer" at 10160.49,7250 h60
  text "Copper" at 11090.23,7250 h60
  text "1.40mil" at 11950,7250 h60
  text "4" at 9750.58,7130 h60
  text "Dielectric1" at 10160.49,7130 h60
  text "FR-4" at 11090.23,7130 h60
  text "59.20mil" at 11950,7130 h60
  text "4.8" at 12599.84,7130 h60
  text "5" at 9750.58,7010 h60
  text "Bottom Layer" at 10160.49,7010 h60
  text "Copper" at 11090.23,7010 h60
  text "1.40mil" at 11950,7010 h60
  text "6" at 9750.58,6890 h60
  text "Bottom Solder" at 10160.49,6890 h60
  text "Solder Resist" at 11090.23,6890 h60
  text "0.40mil" at 11950,6890 h60
  text "3.5" at 12599.84,6890 h60
  text "7" at 9750.58,6770 h60
  text "Bottom Overlay" at 10160.49,6770 h60
  text ".Layer_Name" at 577,-858.49 h60
M13 Component Bodies Top:
  text ".Layer_Name" at 577,-858.49 h60
M14 Component Bodies Bottom:
  text ".Layer_Name" at 577,-858.49 h60
M15 Courtyards Top:
  text ".Layer_Name" at 577,-858.49 h60
M16 Courtyards Bottom:
  text ".Layer_Name" at 577,-858.49 h60
Drill Drawing:
  drawing of 373 lines, arcs and shapes, not listed
  text "Symbol" at 107.5,7802.5 h72
  text "Count" at 613.38,7802.5 h72
  text "Hole Size" at 1203.22,7802.5 h72
  text "Plated" at 2352.88,7802.5 h72
  text "Hole Type" at 2858.76,7802.5 h72
  text "Drill Layer Pair" at 3592.56,7802.5 h72
  text "Via/Pad" at 5092.11,7802.5 h72
  text "Pad Shape" at 5681.96,7802.5 h72
  text "Template" at 6427.76,7802.5 h72
  text "Description" at 7077.59,7802.5 h72
  text "Hole Tolerance (+)" at 7931.35,7802.5 h72
  text "Hole Tolerance (-)" at 9264.96,7802.5 h72
  text "2" at 613.38,7652.5 h60
  text "33.47mil (0.850mm)" at 1203.22,7652.5 h60
  text "PTH" at 2352.88,7652.5 h60
  text "Round" at 2858.76,7652.5 h60
  text "Top Layer - Bottom Layer" at 3592.56,7652.5 h60
  text "Pad" at 5092.11,7652.5 h60
  text "Rounded" at 5681.96,7652.5 h60
  text "c135h85" at 6427.76,7652.5 h60
  text "2" at 613.38,7502.5 h60
  text "40.00mil (1.016mm)" at 1203.22,7502.5 h60
  text "PTH" at 2352.88,7502.5 h60
  text "Round" at 2858.76,7502.5 h60
  text "Top Layer - Bottom Layer" at 3592.56,7502.5 h60
  text "Pad" at 5092.11,7502.5 h60
  text "Rounded" at 5681.96,7502.5 h60
  text "c203h102" at 6427.76,7502.5 h60
  text "2" at 613.38,7352.5 h60
  text "41.34mil (1.050mm)" at 1203.22,7352.5 h60
  text "PTH" at 2352.88,7352.5 h60
  text "Round" at 2858.76,7352.5 h60
  text "Top Layer - Bottom Layer" at 3592.56,7352.5 h60
  text "Pad" at 5092.11,7352.5 h60
  text "Rounded" at 5681.96,7352.5 h60
  text "c155h105" at 6427.76,7352.5 h60
  text "2" at 613.38,7202.5 h60
  text "49.21mil (1.250mm)" at 1203.22,7202.5 h60
  text "PTH" at 2352.88,7202.5 h60
  text "Round" at 2858.76,7202.5 h60
  text "Top Layer - Bottom Layer" at 3592.56,7202.5 h60
  text "Pad" at 5092.11,7202.5 h60
  text "Rounded" at 5681.96,7202.5 h60
  text "c175h125" at 6427.76,7202.5 h60
  text "A" at 78.41,7192.51 h66.67
  text "2" at 613.38,7052.5 h60
  text "137.80mil (3.500mm)" at 1203.22,7052.5 h60
  text "NPTH" at 2352.88,7052.5 h60
  text "Round" at 2858.76,7052.5 h60
  text "Top Layer - Bottom Layer" at 3592.56,7052.5 h60
  text "Pad" at 5092.11,7052.5 h60
  text "Rounded" at 5681.96,7052.5 h60
  text "c100hn350" at 6427.76,7052.5 h60
  text "3" at 613.38,6902.5 h60
  text "70.00mil (1.778mm)" at 1203.22,6902.5 h60
  text "PTH" at 2352.88,6902.5 h60
  text "Round" at 2858.76,6902.5 h60
  text "Top Layer - Bottom Layer" at 3592.56,6902.5 h60
  text "Pad" at 5092.11,6902.5 h60
  text "Rounded" at 5681.96,6902.5 h60
  text "c267h178" at 6427.76,6902.5 h60
  text "3" at 613.38,6752.5 h60
  text "125.00mil (3.175mm)" at 1203.22,6752.5 h60
  text "PTH" at 2352.88,6752.5 h60
  text "Round" at 2858.76,6752.5 h60
  text "Top Layer - Bottom Layer" at 3592.56,6752.5 h60
  text "Pad" at 5092.11,6752.5 h60
  text "Rounded" at 5681.96,6752.5 h60
  text "c533h318" at 6427.76,6752.5 h60
  text "4" at 613.38,6602.5 h60
  text "43.31mil (1.100mm)" at 1203.22,6602.5 h60
  text "PTH" at 2352.88,6602.5 h60
  text "Round" at 2858.76,6602.5 h60
  text "Top Layer - Bottom Layer" at 3592.56,6602.5 h60
  text "Pad" at 5092.11,6602.5 h60
  text "Rounded" at 5681.96,6602.5 h60
  text "c160h110" at 6427.76,6602.5 h60
  text "4" at 613.38,6452.5 h60
  text "55.12mil (1.400mm)" at 1203.22,6452.5 h60
  text "PTH" at 2352.88,6452.5 h60
  text "Round" at 2858.76,6452.5 h60
  text "Top Layer - Bottom Layer" at 3592.56,6452.5 h60
  text "Pad" at 5092.11,6452.5 h60
  text "(Mixed)" at 5681.96,6452.5 h60
  text "(Mixed)" at 6427.76,6452.5 h60
  text "4" at 613.38,6302.5 h60
  text "82.68mil (2.100mm)" at 1203.22,6302.5 h60
  text "PTH" at 2352.88,6302.5 h60
  text "Round" at 2858.76,6302.5 h60
  text "Top Layer - Bottom Layer" at 3592.56,6302.5 h60
  text "Pad" at 5092.11,6302.5 h60
  text "(Mixed)" at 5681.96,6302.5 h60
  text "(Mixed)" at 6427.76,6302.5 h60
  text "C" at 78.41,6292.51 h66.67
  text "5" at 613.38,6152.5 h60
  text "64.96mil (1.650mm)" at 1203.22,6152.5 h60
  text "PTH" at 2352.88,6152.5 h60
  text "Round" at 2858.76,6152.5 h60
  text "Top Layer - Bottom Layer" at 3592.56,6152.5 h60
  text "Pad" at 5092.11,6152.5 h60
  text "(Mixed)" at 5681.96,6152.5 h60
  text "(Mixed)" at 6427.76,6152.5 h60
  text "6" at 613.38,6002.5 h60
  text "62.00mil (1.575mm)" at 1203.22,6002.5 h60
  text "PTH" at 2352.88,6002.5 h60
  text "Round" at 2858.76,6002.5 h60
  text "Top Layer - Bottom Layer" at 3592.56,6002.5 h60
  text "Pad" at 5092.11,6002.5 h60
  text "(Mixed)" at 5681.96,6002.5 h60
  text "(Mixed)" at 6427.76,6002.5 h60
  text "8" at 613.38,5852.5 h60
  text "35.00mil (0.889mm)" at 1203.22,5852.5 h60
  text "PTH" at 2352.88,5852.5 h60
  text "Round" at 2858.76,5852.5 h60
  text "Top Layer - Bottom Layer" at 3592.56,5852.5 h60
  text "Pad" at 5092.11,5852.5 h60
  text "Rounded" at 5681.96,5852.5 h60
  text "c150h89" at 6427.76,5852.5 h60
  text "8" at 613.38,5702.5 h60
  text "35.43mil (0.900mm)" at 1203.22,5702.5 h60
  text "PTH" at 2352.88,5702.5 h60
  text "Round" at 2858.76,5702.5 h60
  text "Top Layer - Bottom Layer" at 3592.56,5702.5 h60
  text "Pad" at 5092.11,5702.5 h60
  text "Rounded" at 5681.96,5702.5 h60
  text "c140h90" at 6427.76,5702.5 h60
  text "8" at 613.38,5552.5 h60
  text "47.24mil (1.200mm)" at 1203.22,5552.5 h60
  text "PTH" at 2352.88,5552.5 h60
  text "Round" at 2858.76,5552.5 h60
  text "Top Layer - Bottom Layer" at 3592.56,5552.5 h60
  text "Pad" at 5092.11,5552.5 h60
  text "(Mixed)" at 5681.96,5552.5 h60
  text "(Mixed)" at 6427.76,5552.5 h60
  text "8" at 613.38,5402.5 h60
  text "110.24mil (2.800mm)" at 1203.22,5402.5 h60
  text "PTH" at 2352.88,5402.5 h60
  text "Round" at 2858.76,5402.5 h60
  text "Top Layer - Bottom Layer" at 3592.56,5402.5 h60
  text "Pad" at 5092.11,5402.5 h60
  text "Rounded" at 5681.96,5402.5 h60
  text "c457h280" at 6427.76,5402.5 h60
  text "9" at 613.38,5252.5 h60
  text "51.18mil (1.300mm)" at 1203.22,5252.5 h60
  text "PTH" at 2352.88,5252.5 h60
  text "Round" at 2858.76,5252.5 h60
  text "Top Layer - Bottom Layer" at 3592.56,5252.5 h60
  text "Pad" at 5092.11,5252.5 h60
  text "(Mixed)" at 5681.96,5252.5 h60
  text "(Mixed)" at 6427.76,5252.5 h60
  text "B" at 78.41,5242.51 h66.67
  text "18" at 613.38,5102.5 h60
  text "59.06mil (1.500mm)" at 1203.22,5102.5 h60
  text "PTH" at 2352.88,5102.5 h60
  text "Round" at 2858.76,5102.5 h60
  text "Top Layer - Bottom Layer" at 3592.56,5102.5 h60
  text "Pad" at 5092.11,5102.5 h60
  text "(Mixed)" at 5681.96,5102.5 h60
  text "(Mixed)" at 6427.76,5102.5 h60
  text "54" at 613.38,4952.5 h60
  text "10.00mil (0.254mm)" at 1203.22,4952.5 h60
  text "PTH" at 2352.88,4952.5 h60
  text "Round" at 2858.76,4952.5 h60
  text "Top Layer - Bottom Layer" at 3592.56,4952.5 h60
  text "Via" at 5092.11,4952.5 h60
  text "Rounded" at 5681.96,4952.5 h60
  text "v51h25" at 6427.76,4952.5 h60
  text "D" at 78.41,4942.51 h66.67
  text "152 Total" at 613.38,4802.5 h60
  text ".Layer_Name" at 577,-858.49 h60
  text "Symbol" at 7742.33,-2536.84 h72
  text "Quantity" at 8042.9,-2536.84 h72
  text "Finished Hole Size" at 8374.9,-2536.84 h72
  text "Plated" at 9011.46,-2536.84 h72
  text "Hole Type" at 9270.6,-2536.84 h72
  text "Drill Layer Pair" at 9645.76,-2536.84 h72
  text "Hole Tolerance" at 10370.09,-2536.84 h72
  text "2" at 8042.9,-2661.16 h60
  text "137.80mil (3.500mm)" at 8374.9,-2661.16 h60
  text "NPTH" at 9011.46,-2661.16 h60
  text "Round" at 9270.6,-2661.16 h60
  text "Top Layer - Bottom Layer" at 9645.76,-2661.16 h60
  text "54" at 8042.9,-2785.48 h60
  text "10.00mil (0.254mm)" at 8374.9,-2785.48 h60
  text "PTH" at 9011.46,-2785.48 h60
  text "Round" at 9270.6,-2785.48 h60
  text "Top Layer - Bottom Layer" at 9645.76,-2785.48 h60
  text "D" at 7717.05,-2795.47 h55.25
  text "2" at 8042.9,-2909.8 h60
  text "33.47mil (0.850mm)" at 8374.9,-2909.8 h60
  text "PTH" at 9011.46,-2909.8 h60
  text "Round" at 9270.6,-2909.8 h60
  text "Top Layer - Bottom Layer" at 9645.76,-2909.8 h60
  text "8" at 8042.9,-3034.12 h60
  text "35.00mil (0.889mm)" at 8374.9,-3034.12 h60
  text "PTH" at 9011.46,-3034.12 h60
  text "Round" at 9270.6,-3034.12 h60
  text "Top Layer - Bottom Layer" at 9645.76,-3034.12 h60
  text "8" at 8042.9,-3158.44 h60
  text "35.43mil (0.900mm)" at 8374.9,-3158.44 h60
  text "PTH" at 9011.46,-3158.44 h60
  text "Round" at 9270.6,-3158.44 h60
  text "Top Layer - Bottom Layer" at 9645.76,-3158.44 h60
  text "2" at 8042.9,-3282.76 h60
  text "40.00mil (1.016mm)" at 8374.9,-3282.76 h60
  text "PTH" at 9011.46,-3282.76 h60
  text "Round" at 9270.6,-3282.76 h60
  text "Top Layer - Bottom Layer" at 9645.76,-3282.76 h60
  text "2" at 8042.9,-3407.08 h60
  text "41.34mil (1.050mm)" at 8374.9,-3407.08 h60
  text "PTH" at 9011.46,-3407.08 h60
  text "Round" at 9270.6,-3407.08 h60
  text "Top Layer - Bottom Layer" at 9645.76,-3407.08 h60
  text "4" at 8042.9,-3531.4 h60
  text "43.31mil (1.100mm)" at 8374.9,-3531.4 h60
  text "PTH" at 9011.46,-3531.4 h60
  text "Round" at 9270.6,-3531.4 h60
  text "Top Layer - Bottom Layer" at 9645.76,-3531.4 h60
  text "8" at 8042.9,-3655.72 h60
  text "47.24mil (1.200mm)" at 8374.9,-3655.72 h60
  text "PTH" at 9011.46,-3655.72 h60
  text "Round" at 9270.6,-3655.72 h60
  text "Top Layer - Bottom Layer" at 9645.76,-3655.72 h60
  text "2" at 8042.9,-3780.04 h60
  text "49.21mil (1.250mm)" at 8374.9,-3780.04 h60
  text "PTH" at 9011.46,-3780.04 h60
  text "Round" at 9270.6,-3780.04 h60
  text "Top Layer - Bottom Layer" at 9645.76,-3780.04 h60
  text "A" at 7717.05,-3790.03 h55.25
  text "9" at 8042.9,-3904.36 h60
  text "51.18mil (1.300mm)" at 8374.9,-3904.36 h60
  text "PTH" at 9011.46,-3904.36 h60
  text "Round" at 9270.6,-3904.36 h60
  text "Top Layer - Bottom Layer" at 9645.76,-3904.36 h60
  text "B" at 7717.05,-3914.35 h55.25
  text "4" at 8042.9,-4028.68 h60
  text "55.12mil (1.400mm)" at 8374.9,-4028.68 h60
  text "PTH" at 9011.46,-4028.68 h60
  text "Round" at 9270.6,-4028.68 h60
  text "Top Layer - Bottom Layer" at 9645.76,-4028.68 h60
  text "18" at 8042.9,-4153 h60
  text "59.06mil (1.500mm)" at 8374.9,-4153 h60
  text "PTH" at 9011.46,-4153 h60
  text "Round" at 9270.6,-4153 h60
  text "Top Layer - Bottom Layer" at 9645.76,-4153 h60
  text "6" at 8042.9,-4277.32 h60
  text "62.00mil (1.575mm)" at 8374.9,-4277.32 h60
  text "PTH" at 9011.46,-4277.32 h60
  text "Round" at 9270.6,-4277.32 h60
  text "Top Layer - Bottom Layer" at 9645.76,-4277.32 h60
  text "5" at 8042.9,-4401.64 h60
  text "64.96mil (1.650mm)" at 8374.9,-4401.64 h60
  text "PTH" at 9011.46,-4401.64 h60
  text "Round" at 9270.6,-4401.64 h60
  text "Top Layer - Bottom Layer" at 9645.76,-4401.64 h60
  text "3" at 8042.9,-4525.96 h60
  text "70.00mil (1.778mm)" at 8374.9,-4525.96 h60
  text "PTH" at 9011.46,-4525.96 h60
  text "Round" at 9270.6,-4525.96 h60
  text "Top Layer - Bottom Layer" at 9645.76,-4525.96 h60
  text "4" at 8042.9,-4650.28 h60
  text "82.68mil (2.100mm)" at 8374.9,-4650.28 h60
  text "PTH" at 9011.46,-4650.28 h60
  text "Round" at 9270.6,-4650.28 h60
  text "Top Layer - Bottom Layer" at 9645.76,-4650.28 h60
  text "C" at 7717.05,-4660.27 h55.25
  text "8" at 8042.9,-4774.6 h60
  text "110.24mil (2.800mm)" at 8374.9,-4774.6 h60
  text "PTH" at 9011.46,-4774.6 h60
  text "Round" at 9270.6,-4774.6 h60
  text "Top Layer - Bottom Layer" at 9645.76,-4774.6 h60
  text "3" at 8042.9,-4898.92 h60
  text "125.00mil (3.175mm)" at 8374.9,-4898.92 h60
  text "PTH" at 9011.46,-4898.92 h60
  text "Round" at 9270.6,-4898.92 h60
  text "Top Layer - Bottom Layer" at 9645.76,-4898.92 h60
  text "152 Total" at 8042.9,-5023.24 h60
M17 Embedded Cavity:
  text ".Layer_Name" at 577,-858.49 h60
M18 Embedded Assembly:
  text ".Layer_Name" at 577,-858.49 h60
M19 Embedded Keepout:
  text ".Layer_Name" at 577,-858.49 h60

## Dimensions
0,-400 to 1000,-400 on M2 Board Dimensions
0,0 to 0,4700 on M2 Board Dimensions
0,0 to 5900,0 on M2 Board Dimensions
